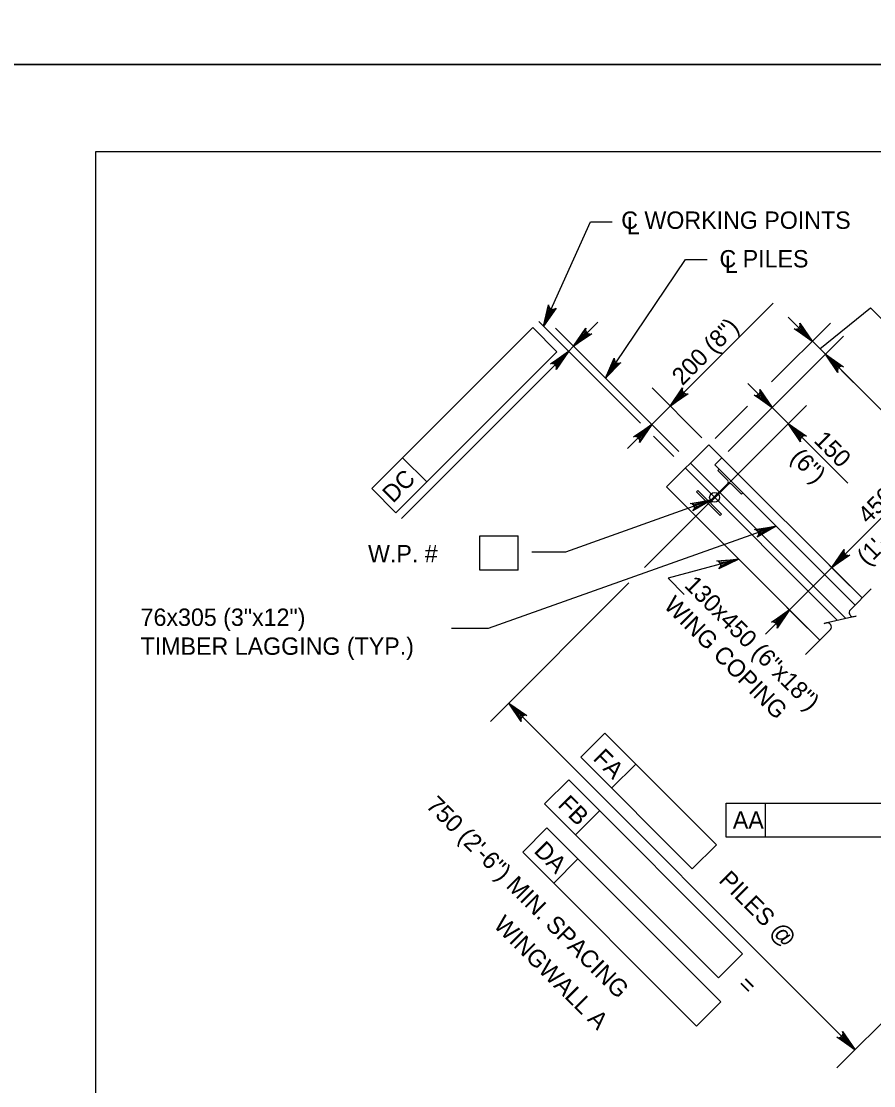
# Model space of a CAD drawing. Extents: x 635440 to 640306, y 296653 to 298484.
# Drawn here: x 639303.6 to 639451, y 297665 to 297849 of the extents above; entities that cross this region are included whole.
import ezdxf

# ---------------------------------------------------------------- set-up
doc = ezdxf.new("R2010")
doc.units = 0
for name, color, linetype in [('2', 7, 'Continuous'), ('3', 7, 'Continuous'), ('4', 7, 'Continuous'), ('5', 7, 'Continuous'), ('52', 7, 'Continuous'), ('8', 7, 'Continuous'), ('PLT-BNDY', 7, 'Continuous')]:
    doc.layers.add(name, color=color, linetype=linetype)

# ---------------------------------------------------------------- blocks, each defined once
blk = doc.blocks.new('HPILE')
at = {"layer": '3'}
for p, q in [((-0.12, -2.66), (-0.12, 2.66)), ((0.12, 2.66), (0.12, -2.66)), ((-3.67, -3.1), (-0.56, -3.1))]:
    blk.add_line(p, q, dxfattribs=at)
for points in [[(-0.56, 3.1), (-3.67, 3.1), (-3.67, 3.54), (3.67, 3.54), (3.67, 3.1), (0.56, 3.1)], [(0.56, -3.1), (3.67, -3.1), (3.67, -3.54), (-3.67, -3.54), (-3.67, -3.1)]]:
    blk.add_lwpolyline(points, dxfattribs=at)
for centre, start, end in [((-0.56, 2.66), 0, 90), ((0.56, 2.66), 90, 180), ((-0.56, -2.66), 270, 0), ((0.56, -2.66), 180, 270)]:
    blk.add_arc(centre, 0.438, start, end, dxfattribs=at)

msp = doc.modelspace()

# ---------------------------------------------------------------- linework, layer by layer
at = {"layer": '2'}
for p, q in [((639316.46, 297262.46), (639316.46, 297826.46)), ((639316.46, 297826.46), (640102.46, 297826.46)), ((639422.46, 297775.77), (639415.15, 297768.47)), ((639448.96, 297749.28), (639422.46, 297775.77)), ((639441.65, 297741.97), (639415.15, 297768.47))]:
    msp.add_line(p, q, dxfattribs=at)
at = {"layer": '3'}
for p in [(639424.72, 297773.51), (639447.74, 297748.06)]:
    msp.add_line(p, (639423.5, 297772.29), dxfattribs=at)
at = {"layer": '4'}
for p, q in [((639401.98, 297814.29), (639405.75, 297814.29)), ((639418.43, 297807.79), (639422.18, 297807.79)), ((639415.78, 297782.45), (639433.56, 297800.23)), ((639441.66, 297792.34), (639450.43, 297799.41)), ((639450.43, 297799.41), (639465.66, 297784.18)), ((639410.65, 297779.47), (639393.06, 297797.06)), ((639399.08, 297792.78), (639403.26, 297796.95)), ((639433.29, 297786.61), (639443.48, 297796.79)), ((639442.61, 297791.4), (639436.17, 297797.83)), ((639364.16, 297768.17), (639392, 297796.01)), ((639392, 297796.01), (639396.18, 297791.83)), ((639412.39, 297779.47), (639395.95, 297795.91)), ((639440.34, 297793.66), (639437.73, 297796.27)), ((639399.08, 297792.78), (639398.21, 297791.9)), ((639425.81, 297774.6), (639445.74, 297794.53)), ((639368.34, 297763.99), (639396.18, 297791.83)), ((639398.21, 297791.9), (639369.32, 297763.01)), ((639501.95, 297732.05), (639442.61, 297791.4)), ((639445.39, 297788.61), (639447.48, 297786.52)), ((639417.26, 297774.6), (639406.13, 297785.72)), ((639421.26, 297776.97), (639412.65, 297785.58)), ((639433.4, 297782.19), (639429.23, 297786.37)), ((639425.81, 297774.6), (639436.53, 297785.32)), ((639439.32, 297782.54), (639411.32, 297754.54)), ((639412.59, 297779.26), (639415.78, 297782.45)), ((639423.55, 297776.86), (639429.13, 297782.45)), ((639433.4, 297782.19), (639436.18, 297779.41)), ((639412.59, 297779.26), (639408.42, 297775.09)), ((639436.18, 297779.41), (639446.47, 297769.12)), ((639416.39, 297773.72), (639412.87, 297777.24)), ((639369.51, 297773.51), (639373.69, 297769.34)), ((639446.14, 297745.72), (639419.27, 297772.59)), ((639444.72, 297745.4), (639418.4, 297771.71)), ((639443.71, 297754.52), (639459.54, 297770.36)), ((639364.16, 297768.17), (639368.34, 297763.99)), ((639382.89, 297760.02), (639389.48, 297760.02)), ((639382.89, 297754.11), (639382.89, 297760.02)), ((639389.48, 297754.11), (639389.48, 297760.02)), ((639389.48, 297754.11), (639382.89, 297754.11)), ((639436.4, 297747.21), (639443.71, 297754.52)), ((639443.27, 297754.96), (639446.84, 297751.39)), ((639408.65, 297751.87), (639384.73, 297727.95)), ((639436.4, 297747.21), (639432.23, 297743.04)), ((639435.96, 297747.65), (639439.53, 297744.08)), ((639447.74, 297671.19), (639387.86, 297731.08)), ((639404.47, 297725.92), (639400.3, 297721.74)), ((639404.47, 297725.92), (639423.77, 297706.62)), ((639400.3, 297721.74), (639419.59, 297702.44)), ((639409.82, 297720.57), (639405.64, 297716.39)), ((639398.23, 297717.85), (639394.06, 297713.68)), ((639398.23, 297717.85), (639428.3, 297687.78)), ((639394.06, 297713.68), (639424.12, 297683.61)), ((639425.43, 297713.83), (639460.73, 297713.83)), ((639425.43, 297707.92), (639425.43, 297713.83)), ((639432.27, 297707.92), (639432.27, 297713.83)), ((639403.58, 297712.51), (639399.4, 297708.33)), ((639394.46, 297709.52), (639390.28, 297705.34)), ((639394.46, 297709.52), (639424.52, 297679.45)), ((639423.77, 297706.62), (639419.59, 297702.44)), ((639460.73, 297707.92), (639425.43, 297707.92)), ((639390.28, 297705.34), (639420.35, 297675.27)), ((639482.24, 297705.7), (639444.61, 297668.06)), ((639399.8, 297704.17), (639395.63, 297699.99)), ((639428.3, 297687.78), (639424.12, 297683.61)), ((639424.52, 297679.45), (639420.35, 297675.27))]:
    msp.add_line(p, q, dxfattribs=at)
for points in [[(639393.87, 297796.24), (639401.98, 297814.29)], [(639404.61, 297787.25), (639418.43, 297807.79)], [(639393.87, 297796.24), (639394.76, 297799.93), (639394.82, 297799.59), (639394.99, 297799.35), (639395.2, 297799.21), (639395.45, 297799.15), (639395.74, 297799.18), (639396.04, 297799.36), (639393.87, 297796.24), (639395.74, 297799.18), (639395.45, 297799.15), (639393.87, 297796.24), (639395.2, 297799.21), (639394.99, 297799.35), (639393.87, 297796.24), (639394.82, 297799.59)], [(639440.34, 297793.66), (639437.21, 297795.8), (639437.56, 297795.74), (639437.84, 297795.81), (639438.04, 297795.96), (639438.19, 297796.16), (639438.26, 297796.44), (639438.2, 297796.79), (639440.34, 297793.66), (639438.26, 297796.44), (639438.19, 297796.16), (639440.34, 297793.66), (639438.04, 297795.96), (639437.84, 297795.81), (639440.34, 297793.66), (639437.56, 297795.74)], [(639399.08, 297792.78), (639401.22, 297795.91), (639401.16, 297795.56), (639401.24, 297795.28), (639401.38, 297795.08), (639401.59, 297794.93), (639401.87, 297794.86), (639402.21, 297794.92), (639399.08, 297792.78), (639401.87, 297794.86), (639401.59, 297794.93), (639399.08, 297792.78), (639401.38, 297795.08), (639401.24, 297795.28), (639399.08, 297792.78), (639401.16, 297795.56)], [(639398.21, 297791.9), (639396.07, 297788.77), (639396.13, 297789.12), (639396.06, 297789.4), (639395.91, 297789.61), (639395.7, 297789.75), (639395.42, 297789.82), (639395.08, 297789.76), (639398.21, 297791.9), (639395.42, 297789.82), (639395.7, 297789.75), (639398.21, 297791.9), (639395.91, 297789.61), (639396.06, 297789.4), (639398.21, 297791.9), (639396.13, 297789.12)], [(639442.61, 297791.4), (639445.74, 297789.25), (639445.39, 297789.32), (639445.11, 297789.24), (639444.9, 297789.1), (639444.76, 297788.89), (639444.69, 297788.61), (639444.75, 297788.26), (639442.61, 297791.4), (639444.69, 297788.61), (639444.76, 297788.89), (639442.61, 297791.4), (639444.9, 297789.1), (639445.11, 297789.24), (639442.61, 297791.4), (639445.39, 297789.32)], [(639404.61, 297787.25), (639406.11, 297790.73), (639406.12, 297790.38), (639406.24, 297790.12), (639406.43, 297789.94), (639406.66, 297789.84), (639406.95, 297789.82), (639407.27, 297789.95), (639404.61, 297787.25), (639406.95, 297789.82), (639406.66, 297789.84), (639404.61, 297787.25), (639406.43, 297789.94), (639406.24, 297790.12), (639404.61, 297787.25), (639406.12, 297790.38)], [(639415.78, 297782.45), (639417.92, 297785.58), (639417.86, 297785.24), (639417.93, 297784.96), (639418.08, 297784.75), (639418.29, 297784.6), (639418.57, 297784.53), (639418.91, 297784.59), (639415.78, 297782.45), (639418.57, 297784.53), (639418.29, 297784.6), (639415.78, 297782.45), (639418.08, 297784.75), (639417.93, 297784.96), (639415.78, 297782.45), (639417.86, 297785.24)], [(639433.4, 297782.19), (639430.27, 297784.33), (639430.61, 297784.27), (639430.9, 297784.34), (639431.1, 297784.49), (639431.25, 297784.7), (639431.32, 297784.98), (639431.26, 297785.32), (639433.4, 297782.19), (639431.32, 297784.98), (639431.25, 297784.7), (639433.4, 297782.19), (639431.1, 297784.49), (639430.9, 297784.34), (639433.4, 297782.19), (639430.61, 297784.27)], [(639412.59, 297779.26), (639410.45, 297776.13), (639410.51, 297776.48), (639410.44, 297776.76), (639410.3, 297776.97), (639410.09, 297777.11), (639409.81, 297777.18), (639409.46, 297777.12), (639412.59, 297779.26), (639409.81, 297777.18), (639410.09, 297777.11), (639412.59, 297779.26), (639410.3, 297776.97), (639410.44, 297776.76), (639412.59, 297779.26), (639410.51, 297776.48)], [(639436.18, 297779.41), (639439.32, 297777.27), (639438.97, 297777.33), (639438.69, 297777.26), (639438.48, 297777.11), (639438.34, 297776.9), (639438.26, 297776.62), (639438.33, 297776.28), (639436.18, 297779.41), (639438.26, 297776.62), (639438.34, 297776.9), (639436.18, 297779.41), (639438.48, 297777.11), (639438.69, 297777.26), (639436.18, 297779.41), (639438.97, 297777.33)], [(639423, 297766.22), (639397.65, 297757.2), (639391.85, 297757.2)], [(639423, 297766.22), (639419.72, 297764.31), (639419.93, 297764.6), (639419.98, 297764.88), (639419.94, 297765.13), (639419.82, 297765.35), (639419.59, 297765.54), (639419.25, 297765.63), (639423, 297766.22), (639419.59, 297765.54), (639419.82, 297765.35), (639423, 297766.22), (639419.94, 297765.13), (639419.98, 297764.88), (639423, 297766.22), (639419.93, 297764.6)], [(639434.1, 297761.69), (639384.28, 297743.98), (639377.94, 297743.98)], [(639427.63, 297755.99), (639415.43, 297752.68), (639418.21, 297749.9)], [(639443.71, 297754.52), (639445.85, 297757.65), (639445.79, 297757.31), (639445.86, 297757.03), (639446.01, 297756.82), (639446.21, 297756.68), (639446.5, 297756.6), (639446.84, 297756.67), (639443.71, 297754.52), (639446.5, 297756.6), (639446.21, 297756.68), (639443.71, 297754.52), (639446.01, 297756.82), (639445.86, 297757.03), (639443.71, 297754.52), (639445.79, 297757.31)], [(639436.4, 297747.21), (639434.26, 297744.08), (639434.32, 297744.43), (639434.25, 297744.71), (639434.1, 297744.92), (639433.9, 297745.06), (639433.61, 297745.14), (639433.27, 297745.07), (639436.4, 297747.21), (639433.61, 297745.14), (639433.9, 297745.06), (639436.4, 297747.21), (639434.1, 297744.92), (639434.25, 297744.71), (639436.4, 297747.21), (639434.32, 297744.43)], [(639387.86, 297731.08), (639390.99, 297728.94), (639390.65, 297729), (639390.36, 297728.93), (639390.16, 297728.78), (639390.01, 297728.57), (639389.94, 297728.29), (639390, 297727.95), (639387.86, 297731.08), (639389.94, 297728.29), (639390.01, 297728.57), (639387.86, 297731.08), (639390.16, 297728.78), (639390.36, 297728.93), (639387.86, 297731.08), (639390.65, 297729)], [(639447.74, 297671.19), (639444.61, 297673.34), (639444.95, 297673.27), (639445.24, 297673.35), (639445.44, 297673.49), (639445.59, 297673.7), (639445.66, 297673.98), (639445.6, 297674.33), (639447.74, 297671.19), (639445.66, 297673.98), (639445.59, 297673.7), (639447.74, 297671.19), (639445.44, 297673.49), (639445.24, 297673.35), (639447.74, 297671.19), (639444.95, 297673.27)]]:
    msp.add_lwpolyline(points, dxfattribs=at)
for points in [[(639393.87, 297796.24), (639395.3, 297798.84), (639394.86, 297799.04)], [(639400.82, 297795.21), (639401.52, 297794.52), (639399.08, 297792.78)], [(639438.6, 297796.09), (639437.91, 297795.4), (639440.34, 297793.66)], [(639395.77, 297790.16), (639396.47, 297789.47), (639398.21, 297791.9)], [(639445.04, 297789.66), (639444.35, 297788.96), (639442.61, 297791.4)], [(639404.61, 297787.25), (639406.46, 297789.56), (639406.05, 297789.84)], [(639417.52, 297784.89), (639418.22, 297784.19), (639415.78, 297782.45)], [(639431.66, 297784.63), (639430.97, 297783.93), (639433.4, 297782.19)], [(639410.16, 297777.52), (639410.85, 297776.83), (639412.59, 297779.26)], [(639438.62, 297777.67), (639437.92, 297776.97), (639436.18, 297779.41)], [(639423, 297766.22), (639420.14, 297765.46), (639420.3, 297765)], [(639434.1, 297761.69), (639431.24, 297760.94), (639431.4, 297760.47)], [(639445.45, 297756.96), (639446.15, 297756.26), (639443.71, 297754.52)], [(639433.97, 297745.47), (639434.66, 297744.78), (639436.4, 297747.21)], [(639390.29, 297729.34), (639389.6, 297728.64), (639387.86, 297731.08)], [(639446, 297673.63), (639445.31, 297672.93), (639447.74, 297671.19)]]:
    msp.add_lwpolyline(points, close=True, dxfattribs=at)
msp.add_circle((639423.45, 297766.67), 0.85, dxfattribs=at)
at = {"layer": '52'}
for points in [[(639434.1, 297761.69), (639430.82, 297759.79), (639431.03, 297760.07), (639431.08, 297760.36), (639431.04, 297760.6), (639430.92, 297760.83), (639430.69, 297761.01), (639430.36, 297761.1), (639434.1, 297761.69), (639430.69, 297761.01), (639430.92, 297760.83), (639434.1, 297761.69), (639431.04, 297760.6), (639431.08, 297760.36), (639434.1, 297761.69), (639431.03, 297760.07)], [(639427.63, 297755.99), (639424.21, 297754.34), (639424.44, 297754.6), (639424.51, 297754.89), (639424.49, 297755.14), (639424.38, 297755.37), (639424.17, 297755.57), (639423.84, 297755.69), (639427.63, 297755.99), (639424.17, 297755.57), (639424.38, 297755.37), (639427.63, 297755.99), (639424.49, 297755.14), (639424.51, 297754.89), (639427.63, 297755.99), (639424.44, 297754.6)]]:
    msp.add_lwpolyline(points, dxfattribs=at)
at = {"layer": '8'}
for p, q in [((639450.51, 297750.83), (639446.93, 297747.25)), ((639443.49, 297743.81), (639439.17, 297739.49))]:
    msp.add_line(p, q, dxfattribs=at)
msp.add_lwpolyline([(639447.61, 297746.06), (639447.96, 297746.14), (639442.42, 297744.87), (639442.79, 297744.96)], dxfattribs=at)
for centre, start, end in [((639447.43, 297746.75), 135, 285), ((639442.95, 297744.27), 320.3286, 102.8672)]:
    msp.add_arc(centre, 0.71, start, end, dxfattribs=at)
at = {"layer": 'PLT-BNDY'}
for points in [[(639276.46, 298435.46), (640117.46, 298435.46), (640117.46, 297841.46), (639276.46, 297841.46)], [(639276.46, 297841.46), (640117.46, 297841.46), (640117.46, 297247.46), (639276.46, 297247.46)]]:
    msp.add_lwpolyline(points, close=True, dxfattribs=at)

# ---------------------------------------------------------------- block references
at = {"layer": '3', "xscale": 0.78743606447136, "yscale": 0.7874360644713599, "rotation": -45.00000000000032}
msp.add_blockref('HPILE', (639424.32, 297767.54), dxfattribs=at)

# ---------------------------------------------------------------- texts
at = {"layer": '4'}
for s, height, p in [('C WORKING POINTS', 3.0001, (639407.31, 297813.08)), ('L', 3, (639408.29, 297812.13)), ('C PILES', 3, (639424.3, 297806.41)), ('L', 3, (639425.23, 297805.44)), ('W.P. # ', 3, (639363.53, 297755.44)), ('AA', 3, (639426.61, 297709.4))]:
    msp.add_text(s, height=height, dxfattribs=at).set_placement(p)
for s, height, rotation, p in [('200 (8")', 3, 45, (639417.88, 297785.86)), ('DC', 3, 45, (639367.83, 297765.54)), ('FA', 3, 314.9382, (639402.28, 297721.39)), ('750 (2\'-6") MIN. SPACING', 3.0001, 315, (639373.41, 297713.23)), ('FB', 3, 314.9382, (639396.22, 297713.35)), ('DA', 3, 314.9382, (639392.07, 297705.39)), ('PILES @', 3, 314.9382, (639424.02, 297700.31)), ('WINGWALL A', 3, 315, (639385.08, 297692.56)), ('=', 3, 314.9382, (639427.25, 297682.18))]:
    msp.add_text(s, height=height, rotation=rotation, dxfattribs=at).set_placement(p)
at = {"layer": '5'}
for s, height, rotation, p in [('150', 3, 315, (639440.45, 297776.33)), ('(6")', 3, 315, (639436.39, 297773.32)), ('450', 3, 45, (639450.04, 297761.91)), ('(1\'-6")', 3, 45, (639449.89, 297754.69)), ('130x450 (6"x18")', 3.0001, 315, (639418.04, 297751.3)), ('WING COPING', 3.0001, 315, (639414.51, 297747.77))]:
    msp.add_text(s, height=height, rotation=rotation, dxfattribs=at).set_placement(p)
for s, p in [('76x305 (3"x12")', (639324.21, 297744.45)), ('TIMBER LAGGING (TYP.)', (639324.21, 297739.45))]:
    msp.add_text(s, height=3.0001, dxfattribs=at).set_placement(p)

doc.saveas('drawing.dxf')
